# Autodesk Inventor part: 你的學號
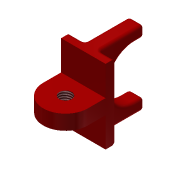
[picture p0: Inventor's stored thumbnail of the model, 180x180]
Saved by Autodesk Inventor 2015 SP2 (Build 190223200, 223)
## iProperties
Created: 2020-03
Part Number: 你的學號
Material: 一般
Document SubType Name: Modeling
Designer: Kuan-Lun Hsu
Density: 1 g/cm^3
Appearance: Smooth - Red
Author: 你的姓名
Title: 基本三視圖
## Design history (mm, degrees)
sketch "Sketch1"
  geometry: L1 (-15, 12)-(15, 12); L2 (15, 12)-(15, 0); L3 (15, 0)-(-15, 0); L4 (-15, 0)-(-15, 12); A1 r 15 centre (0, 12) between (15, 12) and (-15, 12); 2 further points
  constraints: 8 end point, 2 midpoint, 2 parallel, 2 point on circle, 1 centre point, 1 coincident, 1 horizontal, 1 perpendicular
  dimensions: "d0" = 30 distance of L1.start L1.end; "d1" = 12 distance of L1.start L3.end
extrude "Extrusion1" new body sketch "Sketch1" stored distance "d2" = 10; taper "d3" = 0 deg
sketch "Sketch2"
  geometry: L1 (15, 0)-(15, 12) reference; L2 (-15, 12)-(-15, 0) reference; L3 (-15, 0)-(15, 0) reference; C1 r 7.5 at (0, 12); A1 r 15 centre (0, 12) between (15, 12) and (-15, 12) reference; 1 further point
  constraints: 1 centre point, 1 coincident
  dimensions: "d4" = 15 diameter of C1
hole "Hole1" sketch "Sketch2" at (0, 12) diameter "d7" = 8.376; stored, may be unused: countersink angle "d11" = 90 deg, drill point angle "d13" = 118 deg; dims "d8" = 20, "d9" = 4, "d10" = 2, "d12" = 27.3
sketch "Sketch3"
  geometry: L1 (0, -30)-(30, -30); L2 (30, -30)-(30, 20); L3 (30, 20)-(0, 20); L4 (0, 20)-(0, -30); L5 (0, -30)-(30, 20); L6 (30, -30)-(0, 20); L7 (0, 0)-(30, 0) reference; L8 (0, -10)-(0, 0) reference; 1 further point
  constraints: 12 end point, 2 midpoint, 2 parallel, 1 collinear, 1 horizontal, 1 perpendicular
  dimensions: "d14" = 20 distance between parallel lines of L3 L7
extrude "Extrusion3" join sketch "Sketch3" distance "d15" = 6; taper "d16" = 0 deg
sketch "Sketch4"
  geometry: L1 (-6, 25)-(-36, 25); L2 (-36, 25)-(-36, -25); L3 (-36, -25)-(-6, -25); L4 (-6, -25)-(-6, 25); L5 (-6, 25)-(-6, -25) reference; L6 (0, 25)-(-6, 25) reference; L7 (-30, 17.5)-(-36, 17.5); L8 (-36, 17.5)-(-36, -17.5); L9 (-36, -17.5)-(-30, -17.5); L10 (-30, -17.5)-(-30, 17.5); A1 r 17.5 centre (-30, 0) between (-30, -17.5) and (-30, 17.5); 3 further points
  constraints: 16 end point, 5 midpoint, 4 parallel, 2 horizontal, 2 perpendicular, 2 point on circle, 1 centre point, 1 collinear
  dimensions: "d20" = 30 distance between parallel lines of L2 L5; "d21" = 6 distance of L7.start L7.end; "d22" = 35 diameter of A1
extrude "Extrusion4" join sketch "Sketch4" stored distance "d23" = 10; taper "d24" = 0 deg
fillet "Fillet2" dims "d26" = 2
fillet "Fillet3" dims "d27" = 2
body "Solid1"
node "Projected Loop1"
